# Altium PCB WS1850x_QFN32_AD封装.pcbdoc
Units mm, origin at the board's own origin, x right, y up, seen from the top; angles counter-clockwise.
Board outline 35.41 x 31.45 mm, 2 copper layers (Top Layer, Bottom Layer); 1 components, 0 nets, 33 pads, 0 vias.
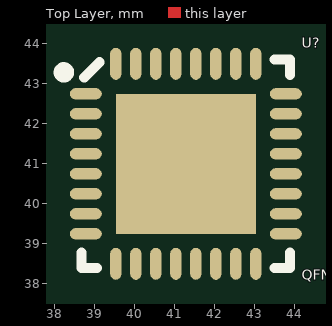
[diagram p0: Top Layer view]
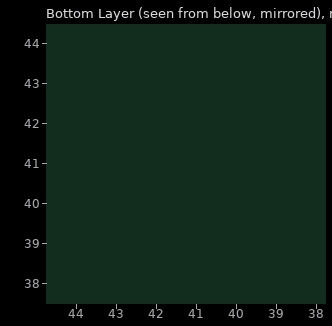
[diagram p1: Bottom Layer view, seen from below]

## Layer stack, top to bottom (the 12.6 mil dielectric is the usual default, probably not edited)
Top Layer: signal copper (thickness not stored)
Dielectric: dielectric 0.32, FR-4, Dk 4.8
Bottom Layer: signal copper (thickness not stored)

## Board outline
60.812,25.4 25.4,25.4 25.4,56.854 60.812,56.854

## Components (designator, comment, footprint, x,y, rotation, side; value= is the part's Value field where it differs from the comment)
U? "QFN-32_L5.0-W5.0-P0.50-TL-EP3.5" QFN-32_L5.0-W5.0-P0.50-TL-EP3.5 41.138,41 r0 top

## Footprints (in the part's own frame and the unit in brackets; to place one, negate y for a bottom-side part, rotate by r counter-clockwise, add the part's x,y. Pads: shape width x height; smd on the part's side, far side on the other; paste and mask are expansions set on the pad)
QFN-32_L5.0-W5.0-P0.50-TL-EP3.5 [mm]
  oval 0.8x0.28 smd paste-100 mask+0.051: 1(-2.363,1.75) 2(-2.363,1.25) 3(-2.363,0.75) 4(-2.363,0.25) 5(-2.363,-0.25) 6(-2.363,-0.75) 7(-2.363,-1.25) 8(-2.363,-1.75) 17(2.638,-1.75) 18(2.638,-1.25) 19(2.638,-0.75) 20(2.638,-0.25) 21(2.638,0.25) 22(2.638,0.75) 23(2.638,1.25) 24(2.638,1.75)
  oval 0.28x0.8 smd paste-100 mask+0.051: 9(-1.612,-2.5) 10(-1.112,-2.5) 11(-0.612,-2.5) 12(-0.112,-2.5) 13(0.388,-2.5) 14(0.888,-2.5) 15(1.388,-2.5) 16(1.888,-2.5) 25(1.887,2.5) 26(1.387,2.5) 27(0.887,2.5) 28(0.387,2.5) 29(-0.113,2.5) 30(-0.613,2.5) 31(-1.113,2.5) 32(-1.613,2.5)
  rect 3.5x3.5 smd paste-100 mask+0.051: 33(0.137,0)
  silkscreen extent -3.04,-2.6 2.74,2.6

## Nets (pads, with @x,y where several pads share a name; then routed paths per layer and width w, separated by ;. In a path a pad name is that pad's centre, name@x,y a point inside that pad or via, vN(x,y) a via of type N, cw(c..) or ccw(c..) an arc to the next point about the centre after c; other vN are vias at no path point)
pads on no net: U?.1 U?.2 U?.3 U?.4 U?.5 U?.6 U?.7 U?.8 U?.9 U?.10 U?.11 U?.12 U?.13 U?.14 U?.15 U?.16 U?.17 U?.18 U?.19 U?.20 U?.21 U?.22 U?.23 U?.24 U?.25 U?.26 U?.27 U?.28 U?.29 U?.30 U?.31 U?.32 U?.33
